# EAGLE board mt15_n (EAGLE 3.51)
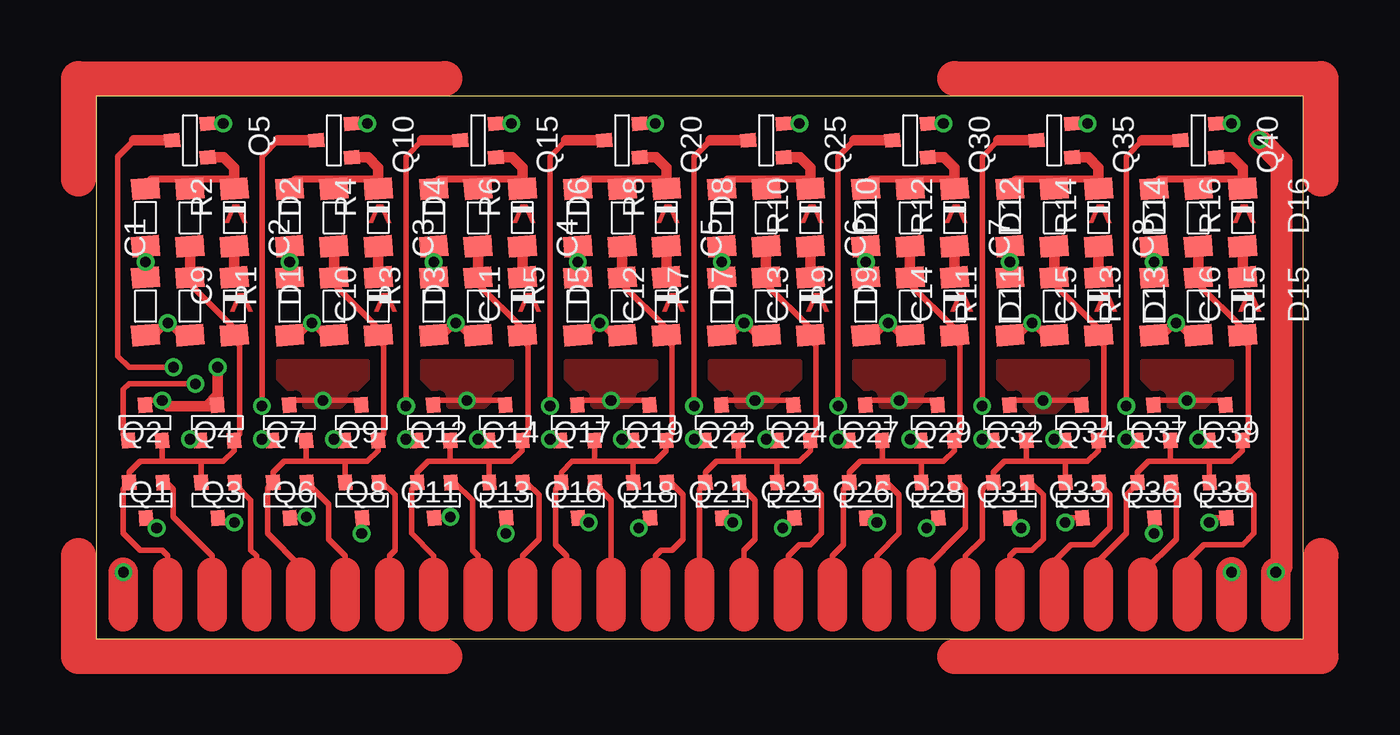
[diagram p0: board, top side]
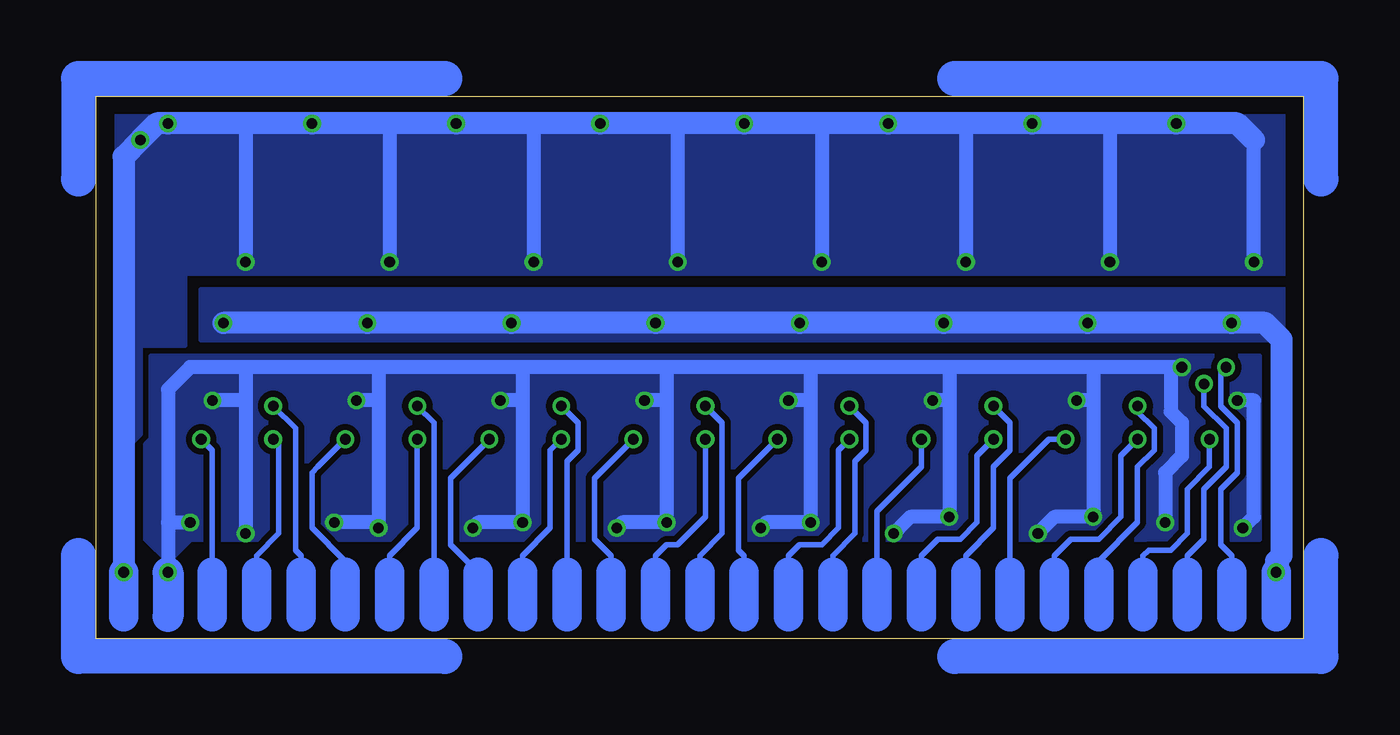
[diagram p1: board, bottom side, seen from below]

Size 69.2 x 31.09 mm. Coordinates in mm from the lower left corner, seen from the top.
Outline: 69.2,0 69.2,31.09 0,31.09 0,0 69.2,0
Copper layers used: Top, Bottom

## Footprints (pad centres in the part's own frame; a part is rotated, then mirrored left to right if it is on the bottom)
04 = smd 1.194 x 1.6 rotated 4.4:  1.651,0 | smd 1.194 x 1.6 rotated 4.3:  -1.651,0
04D = smd 1.194 x 1.6 rotated 4.3:  1.651,0 | smd 1.194 x 1.6 rotated 4.4:  -1.651,0
T-23 = smd 0.787 x 0.889 rotated 4.4:  0.991,1.016 | smd 0.787 x 0.889 rotated 4.3:  -0.94,1.016 | smd 0.787 x 0.889 rotated 4.5:  0.025,-1.016

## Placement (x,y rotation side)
C1  1n  [04]  5.38,24.13 90 top
C2  1n  [04]  13.64,24.13 90 top
C3  1n  [04]  21.89,24.13 90 top
C4  1n  [04]  30.15,24.13 90 top
C5  1n  [04]  38.4,24.13 90 top
C6  1n  [04]  46.66,24.13 90 top
C7  1n  [04]  54.91,24.13 90 top
C8  1n  [04]  63.17,24.13 90 top
C9  100n  [04]  2.84,19.05 270 top
C10  100n  [04]  11.1,19.05 270 top
C11  100n  [04]  19.36,19.05 270 top
C12  100n  [04]  27.61,19.05 270 top
C13  100n  [04]  35.86,19.05 270 top
C14  100n  [04]  44.12,19.05 270 top
C15  100n  [04]  52.38,19.05 270 top
C16  100n  [04]  60.63,19.05 270 top
D1  1N4148  [04D]  7.92,19.05 270 top
D2  1N4148  [04D]  7.92,24.13 270 top
D3  1N4148  [04D]  16.18,19.05 270 top
D4  1N4148  [04D]  16.18,24.13 270 top
D5  1N4148  [04D]  24.44,19.05 270 top
D6  1N4148  [04D]  24.44,24.13 270 top
D7  1N4148  [04D]  32.69,19.05 270 top
D8  1N4148  [04D]  32.69,24.13 270 top
D9  1N4148  [04D]  40.95,19.05 270 top
D10  1N4148  [04D]  40.95,24.13 270 top
D11  1N4148  [04D]  49.2,19.05 270 top
D12  1N4148  [04D]  49.2,24.13 270 top
D13  1N4148  [04D]  57.45,19.05 270 top
D14  1N4148  [04D]  57.45,24.13 270 top
D15  1N4148  [04D]  65.71,19.05 270 top
D16  1N4148  [04D]  65.71,24.13 270 top
Q1  BC857  [T-23]  2.84,12.38 180 top
Q2  BC857  [T-23]  2.84,7.94 0 top
Q3  BC857  [T-23]  6.97,12.38 180 top
Q4  BC857  [T-23]  6.97,7.94 0 top
Q5  BC847  [T-23]  5.38,28.57 270 top
Q6  BC857  [T-23]  11.1,12.38 180 top
Q7  BC857  [T-23]  11.1,7.94 0 top
Q8  BC857  [T-23]  15.23,12.38 180 top
Q9  BC857  [T-23]  15.23,7.94 0 top
Q10  BC847  [T-23]  13.64,28.57 270 top
Q11  BC857  [T-23]  19.36,12.38 180 top
Q12  BC857  [T-23]  19.36,7.94 0 top
Q13  BC857  [T-23]  23.48,12.38 180 top
Q14  BC857  [T-23]  23.48,7.94 0 top
Q15  BC847  [T-23]  21.89,28.57 270 top
Q16  BC857  [T-23]  27.61,12.38 180 top
Q17  BC857  [T-23]  27.61,7.94 0 top
Q18  BC857  [T-23]  31.74,12.38 180 top
Q19  BC857  [T-23]  31.74,7.94 0 top
Q20  BC847  [T-23]  30.15,28.57 270 top
Q21  BC857  [T-23]  35.86,12.38 180 top
Q22  BC857  [T-23]  35.86,7.94 0 top
Q23  BC857  [T-23]  39.99,12.38 180 top
Q24  BC857  [T-23]  39.99,7.94 0 top
Q25  BC847  [T-23]  38.4,28.57 270 top
Q26  BC857  [T-23]  44.12,12.38 180 top
Q27  BC857  [T-23]  44.12,7.94 0 top
Q28  BC857  [T-23]  48.25,12.38 180 top
Q29  BC857  [T-23]  48.25,7.94 0 top
Q30  BC847  [T-23]  46.66,28.57 270 top
Q31  BC857  [T-23]  52.38,12.38 180 top
Q32  BC857  [T-23]  52.38,7.94 0 top
Q33  BC857  [T-23]  56.5,12.38 180 top
Q34  BC857  [T-23]  56.5,7.94 0 top
Q35  BC847  [T-23]  54.91,28.57 270 top
Q36  BC857  [T-23]  60.63,12.38 180 top
Q37  BC857  [T-23]  60.63,7.94 0 top
Q38  BC857  [T-23]  64.76,12.38 180 top
Q39  BC857  [T-23]  64.76,7.94 0 top
Q40  BC847  [T-23]  63.17,28.57 270 top
R1  390  [04]  5.38,19.05 270 top
R2  820  [04]  2.84,24.13 270 top
R3  390  [04]  13.64,19.05 270 top
R4  820  [04]  11.1,24.13 270 top
R5  390  [04]  21.89,19.05 270 top
R6  820  [04]  19.36,24.13 270 top
R7  390  [04]  30.15,19.05 270 top
R8  820  [04]  27.61,24.13 270 top
R9  390  [04]  38.4,19.05 270 top
R10  820  [04]  35.86,24.13 270 top
R11  390  [04]  46.66,19.05 270 top
R12  820  [04]  44.12,24.13 270 top
R13  390  [04]  54.91,19.05 270 top
R14  820  [04]  52.38,24.13 270 top
R15  390  [04]  63.17,19.05 270 top
R16  820  [04]  60.63,24.13 270 top

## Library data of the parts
C1-C16 Q1-Q40 R1-R16 = SMD
D1-D16 = DM

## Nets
0V: Q1. Q2. Q3. Q4. Q6. Q7. Q8. Q9. Q11. Q12. Q13. Q14. Q16. Q17. Q18. Q19. Q21. Q22. Q23. Q24. Q26. Q27. Q28. Q29. Q31. Q32. Q33. Q34. Q36. Q37. Q38. Q39.
A0: Q1.
A1: Q2.
A2: Q3.
A3: Q4.
AQ: Q5.
AX: C1. D1. Q1. Q2. Q3. Q4. R1.
B0: Q6.
B1: Q7.
B2: Q8.
B3: Q9.
BQ: Q10.
BX: C2. D3. Q6. Q7. Q8. Q9. R3.
C0: Q11.
C1: Q12.
C2: Q13.
C3: Q14.
CQ: Q15.
CX: C3. D5. Q11. Q12. Q13. Q14. R5.
D0: Q16.
D1: Q17.
D2: Q18.
D3: Q19.
DQ: Q20.
DX: C4. D7. Q16. Q17. Q18. Q19. R7.
E0: Q21.
E1: Q22.
E2: Q23.
E3: Q24.
EQ: Q25.
EX: C5. D9. Q21. Q22. Q23. Q24. R9.
F0: Q26.
F1: Q27.
F2: Q28.
F3: Q29.
FQ: Q30.
FX: C6. D11. Q26. Q27. Q28. Q29. R11.
G0: Q31.
G1: Q32.
G2: Q33.
G3: Q34.
GND: C9. C10. C11. C12. C13. C14. C15. C16. Q5. Q10. Q15. Q20. Q25. Q30. Q35. Q40. R2. R4. R6. R8. R10. R12. R14. R16.
GQ: Q35.
GX: C7. D13. Q31. Q32. Q33. Q34. R13.
H0: Q36.
H1: Q37.
H2: Q38.
H3: Q39.
HQ: Q40.
HX: C8. D15. Q36. Q37. Q38. Q39. R15.
N$2: D1. D2.
N$3: C1. D2. Q5. R2.
N$6: D3. D4.
N$7: C2. D4. Q10. R4.
N$11: D5. D6.
N$12: C3. D6. Q15. R6.
N$16: D7. D8.
N$17: C4. D8. Q20. R8.
N$21: D9. D10.
N$22: C5. D10. Q25. R10.
N$26: D11. D12.
N$27: C6. D12. Q30. R12.
N$31: D13. D14.
N$32: C7. D14. Q35. R14.
N$36: D15. D16.
N$37: C8. D16. Q40. R16.
VCC: C9. C10. C11. C12. C13. C14. C15. C16. R1. R3. R5. R7. R9. R11. R13. R15.

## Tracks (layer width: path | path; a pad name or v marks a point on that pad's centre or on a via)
0V  (via drill 0.61 pad 1.02)
  Top 0.305: Q2. 2.91,6.92 v3.48,6.35 | Q7. 11.16,6.92 11.23,6.99 v12.05,6.99 | Q9. 15.29,6.92 15.23,6.86 v15.23,6.03 | Q4. 7.04,6.92 6.97,6.86 7.1,6.86 7.29,6.67 v7.93,6.67 | 23.55,6.92 Q14. 23.48,6.9 v23.48,6.03 | 40.06,6.92 Q24. 39.93,6.92 v39.36,6.35 | 48.31,6.92 Q29. 48.18,6.92 v47.61,6.35 | 64.82,6.92 Q39. 64.06,6.92 v63.81,6.67 | 56.57,6.92 Q34. 55.8,6.92 v55.55,6.67 | Q19. 31.67,6.92 v31.1,6.35 | Q1. 2.91,13.4 3.16,13.65 v3.8,13.65 | Q6. 11.16,13.4 11.42,13.65 v13.01,13.65 14.91,13.65 15.16,13.4 Q8. | Q11. 19.42,13.4 19.67,13.65 v21.26,13.65 23.16,13.65 23.42,13.4 Q13. | Q16. 27.67,13.4 27.93,13.65 v29.51,13.65 31.42,13.65 31.67,13.4 Q18. | Q21. 35.93,13.4 36.18,13.65 v37.77,13.65 39.68,13.65 39.93,13.4 Q23. | Q26. 44.18,13.4 44.44,13.65 v46.03,13.65 47.93,13.65 48.18,13.4 Q28. | Q31. 52.44,13.4 52.69,13.65 v54.28,13.65 56.18,13.65 56.44,13.4 Q33. | Q36. 60.69,13.4 60.95,13.65 v62.53,13.65 64.44,13.65 64.69,13.4 Q38. | Q12. 20.24,6.92 v20.31,6.99 | Q17. 27.99,6.92 v28.25,6.67 | Q22. 36.25,6.92 v36.5,6.67 | Q27. 44.5,6.92 v44.75,6.67 | Q32. 52.44,6.92 v53.01,6.35 | Q37. 60.66,6.06 v60.63,6.03
  Top 0.61: v3.8,13.65 4.12,13.34 6.34,13.34 | Q3. 6.88,13.34 6.34,13.34 | 6.34,13.34 6.97,13.97 v6.97,15.56
  Top 1.778: v65.08,3.81 65.08,1.27
  Bottom 0.813: v3.48,6.35 2.84,6.99 2.84,13.65 v3.8,13.65 | v7.93,6.67 7.93,9.53 6.97,10.48 6.97,12.38 7.61,13.02 7.61,15.56 | v15.23,6.03 14.27,6.99 v12.05,6.99 12.05,13.65 | 12.05,13.65 v13.01,13.65 | 12.05,15.56 12.05,13.65 | 7.61,15.56 12.05,15.56 | v6.97,15.56 7.61,15.56 | 12.05,15.56 20.31,15.56 | 20.31,15.56 28.25,15.56 | 28.25,15.56 36.5,15.56 | 36.5,15.56 44.75,15.56 | 20.31,13.65 v20.31,6.99 22.53,6.99 v23.48,6.03 | 20.31,15.56 20.31,13.65 | 20.31,13.65 v21.26,13.65 | v31.1,6.35 30.78,6.67 v28.25,6.67 28.25,13.65 | 28.25,15.56 28.25,13.65 | 28.25,13.65 v29.51,13.65 | 36.5,13.65 v36.5,6.67 39.04,6.67 v39.36,6.35 | 36.5,15.56 36.5,13.65 | 36.5,13.65 v37.77,13.65 | 44.75,13.65 v44.75,6.67 47.29,6.67 v47.61,6.35 | 44.75,15.56 44.75,13.65 | 44.75,13.65 v46.03,13.65 | 65.08,6.67 65.08,14.29 63.81,15.56 60.63,15.56 | 65.08,6.67 v65.08,3.81 | 44.75,15.56 53.01,15.56 | 53.01,15.56 60.63,15.56 | 53.01,6.67 v53.01,6.35 | 53.01,13.65 53.01,6.67 | 53.01,13.65 v54.28,13.65 | 53.01,15.56 53.01,13.65 | 60.63,13.65 v60.63,6.03 | 60.63,15.56 60.63,13.65 | 60.63,13.65 v62.53,13.65 | 65.08,6.67 v63.81,6.67 | 53.01,6.67 v55.55,6.67
  Bottom 1.778: v65.08,3.81 65.08,1.27
  pour Bottom (isolate 0.356): 65.08,4.45 63.8,5.71 2.53,5.71 2.53,16.19 66.03,16.19 66.03,11.43 66.34,11.11 66.34,5.71
  pour Top (isolate 0.356): 10.46,15.88 15.54,15.88 15.54,14.92 13.96,13.34 12.05,13.34 10.46,14.92
  pour Top (isolate 0.356): 18.72,15.88 18.72,14.92 20.31,13.34 22.21,13.34 23.8,14.92 23.8,15.88
  pour Top (isolate 0.356): 26.98,15.88 32.05,15.88 32.05,14.92 30.47,13.34 28.56,13.34 26.98,14.92
  pour Top (isolate 0.356): 35.23,15.88 35.23,14.92 36.82,13.34 38.72,13.34 40.31,14.92 40.31,15.88
  pour Top (isolate 0.356): 43.48,15.88 48.56,15.88 48.56,14.92 46.98,13.34 45.07,13.34 43.48,14.92
  pour Top (isolate 0.356): 51.74,15.88 56.82,15.88 56.82,14.92 54.91,13.02 53.64,13.02 51.74,14.92
  pour Top (isolate 0.356): 59.99,15.88 65.08,15.88 65.08,14.92 63.49,13.34 61.58,13.34 59.99,14.92
A0  (via drill 0.61 pad 1.02)
  Top 0.305: 1.85,11.37 1.85,11.47 1.57,11.75 1.57,14.29 1.89,14.61 v5.7,14.61
  Bottom 0.305: 6.66,3.81 6.66,4.76 5.7,5.71 5.7,8.57 4.43,9.84 4.43,12.06 5.7,13.34 v5.7,14.61
  Bottom 1.676: 6.66,1.27 6.66,3.81
A1
  Top 0.305: 6.66,3.81 6.66,4.76 4.43,6.99 4.43,8.57 4.05,8.95 3.84,8.95
  Top 1.676: 6.66,1.27 6.66,3.81
A2  (via drill 0.61 pad 1.02)
  Top 0.305: 5.98,11.37 5.45,11.37 v5.38,11.43
  Bottom 0.305: 9.19,3.81 9.19,4.76 8.88,5.08 7.61,5.08 6.66,6.03 6.66,8.57 5.38,9.84 v5.38,11.43
  Bottom 1.676: 9.19,1.27 9.19,3.81
A3
  Top 0.305: 7.96,8.95 7.96,8.85 8.88,7.94 8.88,5.08 9.19,4.76 9.19,3.81
  Top 1.676: 9.19,1.27 9.19,3.81
AQ  (via drill 0.61 pad 1.02)
  Top 0.305: 2.18,28.55 1.26,27.62 1.26,16.19 1.89,15.56 v4.43,15.56
  Top 0.61: 2.18,28.55 Q5.
  Bottom 0.305: 4.12,3.81 4.12,4.76 4.75,5.4 4.75,8.57 3.8,9.53 3.8,12.38 4.75,13.34 4.75,15.24 v4.43,15.56
  Bottom 1.676: 4.12,1.27 4.12,3.81
AX
  Top 0.305: R1. 5.38,20.32 7.93,17.78 7.93,17.4 7.93,17.14 8.24,16.83 8.24,11.75 7.91,11.42 7.91,11.37 7.91,10.78 7.29,10.16 6.02,10.16 | 4.12,3.81 4.12,4.76 3.8,5.08 2.53,5.08 1.57,6.03 1.57,8.57 1.91,8.9 1.91,8.95 1.91,9.54 2.53,10.16 3.8,10.16 | 3.8,10.16 6.02,10.16 | 3.78,11.37 3.8,11.35 3.8,10.16 | 6.03,8.95 6.02,8.97 6.02,10.16
  Top 0.61: R1. C1.
  Top 1.676: 4.12,1.27 4.12,3.81
B0  (via drill 0.61 pad 1.02)
  Top 0.305: 10.11,11.37 9.58,11.37 v9.51,11.43
  Bottom 0.305: 14.27,3.81 14.27,4.76 13.32,5.71 11.74,5.71 10.46,6.99 10.46,10.48 v9.51,11.43
  Bottom 1.676: 14.27,1.27 14.27,3.81
B1
  Top 0.305: 12.09,8.95 13.32,7.72 13.32,5.71 14.27,4.76 14.27,3.81
  Top 1.676: 14.27,1.27 14.27,3.81
B2  (via drill 0.61 pad 1.02)
  Top 0.305: 14.24,11.37 13.7,11.37 v13.64,11.43
  Bottom 0.305: 16.82,3.81 16.82,9.21 14.59,11.43 v13.64,11.43
  Bottom 1.676: 16.82,1.27 16.82,3.81
B3
  Top 0.305: 16.22,8.95 16.43,8.95 17.13,8.26 17.13,5.08 16.82,4.76 16.82,3.81
  Top 1.676: 16.82,1.27 16.82,3.81
BQ  (via drill 0.61 pad 1.02)
  Top 0.305: 10.44,28.55 9.51,27.62 v9.51,13.34
  Top 0.61: 10.44,28.55 Q10.
  Bottom 0.305: 11.74,3.81 11.74,4.45 9.51,6.67 9.51,9.84 8.56,10.79 8.56,12.06 9.51,13.02 v9.51,13.34
  Bottom 1.676: 11.74,1.27 11.74,3.81
BX
  Top 0.305: R3. 13.64,20.32 16.18,17.78 16.18,17.4 16.18,17.14 16.5,16.83 16.5,11.75 16.17,11.42 16.17,11.37 16.17,10.78 15.54,10.16 14.27,10.16 | 11.74,3.81 11.74,4.13 9.83,6.03 9.83,8.62 10.16,8.95 10.16,9.54 10.78,10.16 12.05,10.16 | 12.05,10.16 14.27,10.16 | 12.04,11.37 12.05,11.35 12.05,10.16 | 14.29,8.95 14.27,8.97 14.27,10.16
  Top 0.61: R3. C2.
  Top 1.676: 11.74,1.27 11.74,3.81
C0  (via drill 0.61 pad 1.02)
  Top 0.305: 18.36,11.37 17.83,11.37 v17.77,11.43
  Bottom 0.305: v17.77,11.43 18.72,10.48 18.72,6.67 19.67,5.71 20.94,5.71 21.89,4.76 21.89,3.81
  Bottom 1.676: 21.89,1.27 21.89,3.81
C1
  Top 0.305: 20.35,8.95 20.56,8.95 21.58,7.94 21.58,5.08 21.89,4.76 21.89,3.81
  Top 1.676: 21.89,1.27 21.89,3.81
C2  (via drill 0.61 pad 1.02)
  Top 0.305: 22.49,11.37 21.96,11.37 v21.89,11.43
  Bottom 0.305: 24.44,3.81 24.44,7.3 21.89,9.84 v21.89,11.43
  Bottom 1.676: 24.44,1.27 24.44,3.81
C3
  Top 0.305: 24.47,8.95 24.69,8.95 25.39,8.26 25.39,5.71 24.44,4.76 24.44,3.81
  Top 1.676: 24.44,1.27 24.44,3.81
CQ  (via drill 0.61 pad 1.02)
  Top 0.305: 18.69,28.55 17.77,27.62 v17.77,13.34
  Top 0.61: 18.69,28.55 Q15.
  Bottom 0.305: 19.35,3.81 19.35,4.76 17.77,6.35 17.77,9.84 16.82,10.79 16.82,12.38 v17.77,13.34
  Bottom 1.676: 19.35,1.27 19.35,3.81
CX
  Top 0.305: R5. 21.89,20.32 24.44,17.78 24.44,17.4 24.44,17.14 24.75,16.83 24.75,11.75 24.42,11.42 24.42,11.37 24.42,10.78 23.8,10.16 22.53,10.16 | 20.31,10.16 19.04,10.16 18.42,9.54 18.42,8.95 18.42,8.9 18.09,8.57 18.09,6.03 19.35,4.76 19.35,3.81 | 20.31,10.16 22.53,10.16 | 22.54,8.95 22.53,8.97 22.53,10.16 | 20.29,11.37 20.31,11.35 20.31,10.16
  Top 0.61: R5. C3.
  Top 1.676: 19.35,1.27 19.35,3.81
D0  (via drill 0.61 pad 1.02)
  Top 0.305: 26.62,11.37 26.09,11.37 v26.02,11.43
  Bottom 0.305: 29.51,3.81 29.51,4.76 28.88,5.4 27.61,5.4 26.66,6.35 26.66,10.79 v26.02,11.43
  Bottom 1.676: 29.51,1.27 29.51,3.81
D1
  Top 0.305: 28.6,8.95 28.6,8.85 29.51,7.94 29.51,3.81
  Top 1.676: 29.51,1.27 29.51,3.81
D2  (via drill 0.61 pad 1.02)
  Top 0.305: 30.75,11.37 30.21,11.37 v30.15,11.43
  Bottom 0.305: 32.06,3.81 32.06,4.76 32.37,5.08 32.37,9.21 v30.15,11.43
  Bottom 1.676: 32.06,1.27 32.06,3.81
D3
  Top 0.305: 32.73,8.95 32.94,8.95 33.64,8.26 33.64,5.71 33.01,5.08 32.37,5.08 32.06,4.76 32.06,3.81
  Top 1.676: 32.06,1.27 32.06,3.81
DQ  (via drill 0.61 pad 1.02)
  Top 0.305: 26.95,28.55 26.02,27.62 v26.02,13.34
  Top 0.61: 26.95,28.55 Q20.
  Bottom 0.305: 26.98,3.81 26.98,4.76 25.71,6.03 25.71,10.16 25.07,10.79 25.07,12.38 v26.02,13.34
  Bottom 1.676: 26.98,1.27 26.98,3.81
DX
  Top 0.305: 30.15,20.64 30.15,20.32 32.69,17.78 32.69,17.4 32.69,17.14 33.01,16.83 33.01,11.75 32.68,11.42 32.68,11.37 32.68,10.78 32.06,10.16 30.78,10.16 | 28.56,10.16 27.29,10.16 26.67,9.54 26.67,8.95 26.67,8.9 26.34,8.57 26.34,5.4 26.98,4.76 26.98,3.81 | 28.55,11.37 28.56,11.35 28.56,10.16 | 28.56,10.16 30.78,10.16 | 30.8,8.95 30.78,8.97 30.78,10.16
  Top 0.61: 30.15,20.64 R7. C4.
  Top 1.676: 26.98,1.27 26.98,3.81
E0  (via drill 0.61 pad 1.02)
  Top 0.305: 34.87,11.37 34.34,11.37 v34.28,11.43
  Bottom 0.305: 37.14,3.81 37.14,4.76 36.5,5.4 35.86,5.4 34.28,6.99 v34.28,11.43
  Bottom 1.676: 37.14,1.27 37.14,3.81
E1
  Top 0.305: 36.86,8.95 36.86,8.85 37.77,7.94 37.77,5.71 37.14,5.08 37.14,3.81
  Top 1.676: 37.14,1.27 37.14,3.81
E2  (via drill 0.61 pad 1.02)
  Top 0.305: 39,11.37 38.47,11.37 v38.4,11.43
  Bottom 0.305: 39.68,3.81 39.68,4.76 40.63,5.71 40.63,9.21 v38.4,11.43
  Bottom 1.676: 39.68,1.27 39.68,3.81
E3
  Top 0.305: 40.98,8.95 40.98,8.85 41.58,8.26 41.58,6.03 40.95,5.4 40.31,5.4 39.68,4.76 39.68,3.81
  Top 1.676: 39.68,1.27 39.68,3.81
EQ  (via drill 0.61 pad 1.02)
  Top 0.305: 35.2,28.55 34.28,27.62 v34.28,13.34
  Top 0.61: 35.2,28.55 Q25.
  Bottom 0.305: 34.6,3.81 34.6,4.76 33.32,6.03 33.32,12.38 v34.28,13.34
  Bottom 1.676: 34.6,1.27 34.6,3.81
EX
  Top 0.305: R9. 38.4,20.32 40.95,17.78 40.95,17.4 40.95,17.14 41.26,16.83 41.26,11.75 40.93,11.42 40.93,11.37 40.93,10.78 40.31,10.16 39.04,10.16 | 36.82,10.16 35.55,10.16 34.93,9.54 34.93,8.95 34.93,8.9 34.6,8.57 34.6,3.81 | 36.82,10.16 39.04,10.16 | 36.8,11.37 36.82,11.35 36.82,10.16 | 39.05,8.95 39.04,8.97 39.04,10.16
  Top 0.61: R9. C5.
  Top 1.676: 34.6,1.27 34.6,3.81
F0  (via drill 0.61 pad 1.02)
  Top 0.305: 43.13,11.37 43.07,11.43 v42.53,11.43
  Bottom 0.305: 44.75,3.81 44.75,4.76 43.17,6.35 43.17,10.79 v42.53,11.43
  Bottom 1.676: 44.75,1.27 44.75,3.81
F1
  Top 0.305: 45.11,8.95 45.33,8.95 46.03,8.26 46.03,6.03 44.75,4.76 44.75,3.81
  Top 1.676: 44.75,1.27 44.75,3.81
F2  (via drill 0.61 pad 1.02)
  Top 0.305: 47.26,11.37 47.19,11.43 v46.66,11.43
  Bottom 0.305: 47.29,3.81 48.88,5.4 48.88,9.21 v46.66,11.43
  Bottom 1.676: 47.29,1.27 47.29,3.81
F3
  Top 0.305: 49.24,8.95 49.45,8.95 49.83,8.57 49.83,6.35 47.29,3.81
  Top 1.676: 47.29,1.27 47.29,3.81
FQ  (via drill 0.61 pad 1.02)
  Top 0.305: 43.46,28.55 42.53,27.62 v42.53,13.34
  Top 0.61: 43.46,28.55 Q30.
  Bottom 0.305: 42.21,3.81 42.21,10.16 41.58,10.79 41.58,12.38 v42.53,13.34
  Bottom 1.676: 42.21,1.27 42.21,3.81
FX
  Top 0.305: R11. 46.66,20.32 49.2,17.78 49.2,17.4 49.2,17.14 49.52,16.83 49.52,11.75 49.19,11.42 49.19,11.37 49.19,10.78 48.57,10.16 47.29,10.16 | 45.07,10.16 43.8,10.16 43.18,9.54 43.18,8.95 43.18,8.9 42.85,8.57 42.85,5.4 42.21,4.76 42.21,3.81 | 45.07,10.16 47.29,10.16 | 47.31,8.95 47.29,8.97 47.29,10.16 | 45.06,11.37 45.07,11.35 45.07,10.16
  Top 0.61: R11. C6.
  Top 1.676: 42.21,1.27 42.21,3.81
G0  (via drill 0.61 pad 1.02)
  Top 0.305: 51.38,11.37 50.85,11.37 v50.79,11.43
  Bottom 0.305: 52.38,3.81 52.38,4.76 50.79,6.35 v50.79,11.43
  Bottom 1.676: 52.38,1.27 52.38,3.81
G1
  Top 0.305: 53.37,8.95 53.58,8.95 54.28,8.26 54.28,5.71 53.64,5.08 52.69,5.08 52.38,4.76 52.38,3.81
  Top 1.676: 52.38,1.27 52.38,3.81
G2  (via drill 0.61 pad 1.02)
  Top 0.305: 55.51,11.37 54.98,11.37 v54.92,11.43
  Bottom 0.305: 54.92,3.81 54.92,4.45 56.82,6.35 56.82,9.53 56.5,9.84 v54.92,11.43
  Bottom 1.676: 54.92,1.27 54.92,3.81
G3
  Top 0.305: 57.49,8.95 57.49,8.85 58.09,8.26 58.09,6.35 57.14,5.4 55.87,5.4 54.92,4.45 54.92,3.81
  Top 1.676: 54.92,1.27 54.92,3.81
GND  (via drill 0.61 pad 1.02)
  Top 0.305: 6.4,29.52 7.28,29.52 v7.29,29.53 | 14.66,29.52 15.53,29.52 v15.54,29.53 | 22.91,29.52 23.79,29.52 v23.8,29.53 | 31.17,29.52 32.04,29.52 v32.06,29.53 | 39.42,29.52 40.3,29.52 v40.31,29.53 | 47.68,29.52 48.55,29.52 v48.57,29.53 | 55.93,29.52 56.81,29.52 v56.82,29.53 | 64.19,29.52 65.06,29.52 v65.08,29.53
  Top 0.61: C9. v2.84,21.59 2.84,22.48 | C10. v11.1,21.59 11.1,22.48 | C11. v19.35,21.59 19.35,22.48 | C12. v27.61,21.59 27.61,22.48 | C13. v35.86,21.59 35.86,22.48 | C14. v44.12,21.59 44.12,22.48 | 52.38,20.64 C15. v52.38,21.59 52.38,22.48 | C16. v60.63,21.59 60.63,22.48
  Top 1.27: v67.61,3.81 67.93,4.13 67.93,27.3 v66.66,28.57
  Top 1.676: v67.61,3.81 67.61,1.27
  Bottom 0.813: v2.84,21.59 2.84,28.57 | 11.1,29.53 v11.1,21.59 | 19.35,29.53 v19.35,21.59 | 27.61,29.53 v27.61,21.59 | 35.86,29.53 v35.86,21.59 | 44.12,29.53 v44.12,21.59 | 52.38,29.53 v52.38,21.59 | 60.63,29.53 v60.63,21.59
  Bottom 1.27: v67.61,3.81 67.61,27.62 v66.66,28.57 65.71,29.53 v65.08,29.53 60.63,29.53 v56.82,29.53 52.38,29.53 v48.57,29.53 44.12,29.53 v40.31,29.53 35.86,29.53 v32.06,29.53 27.61,29.53 v23.8,29.53 19.35,29.53 v15.54,29.53 11.1,29.53 v7.29,29.53 3.8,29.53 2.84,28.57
  Bottom 1.676: v67.61,3.81 67.61,1.27
  pour Bottom (isolate 0.356): 0.62,30.48 0.62,20.95 64.12,20.95 64.12,16.83 66.66,16.83 66.66,11.75 67.3,11.11 67.3,0.95 68.57,0.95 68.57,30.48
GQ  (via drill 0.61 pad 1.02)
  Top 0.305: 51.71,28.55 50.79,27.62 v50.79,13.34
  Top 0.61: 51.71,28.55 Q35.
  Bottom 0.305: 49.83,3.81 49.83,12.38 v50.79,13.34
  Bottom 1.676: 49.83,1.27 49.83,3.81
GX
  Top 0.305: R13. 54.92,20.32 57.46,17.78 57.46,17.4 57.46,17.14 57.77,16.83 57.77,11.75 57.44,11.42 57.44,11.37 57.44,10.78 56.82,10.16 55.55,10.16 | 53.33,10.16 52.06,10.16 51.44,9.54 51.44,8.95 51.17,8.95 50.79,8.57 50.79,5.71 49.83,4.76 49.83,3.81 | 53.33,10.16 55.55,10.16 | 55.56,8.95 55.55,8.97 55.55,10.16 | 53.31,11.37 53.33,11.35 53.33,10.16
  Top 0.61: R13. C7.
  Top 1.676: 49.83,1.27 49.83,3.81
H0  (via drill 0.61 pad 1.02)
  Top 0.305: 59.64,11.37 59.11,11.37 v59.04,11.43
  Bottom 0.305: 60,3.81 60,4.76 58.72,6.03 58.72,11.11 v59.04,11.43
  Bottom 1.676: 60,1.27 60,3.81
H1
  Top 0.305: 60,3.81 61.9,5.71 61.9,8.57 61.62,8.85 61.62,8.95
  Top 1.676: 60,1.27 60,3.81
H2  (via drill 0.61 pad 1.02)
  Top 0.305: 63.77,11.37 63.23,11.37 v63.17,11.43
  Bottom 0.305: 62.53,3.81 62.53,10.79 v63.17,11.43
  Bottom 1.676: 62.53,1.27 62.53,3.81
H3
  Top 0.305: 62.53,3.81 62.53,4.45 63.49,5.4 65.71,5.4 66.35,6.03 66.35,8.26 65.75,8.85 65.75,8.95
  Top 1.676: 62.53,1.27 62.53,3.81
HQ  (via drill 0.61 pad 1.02)
  Top 0.305: 59.97,28.55 59.04,27.62 v59.04,13.34
  Top 0.61: 59.97,28.55 Q40.
  Bottom 0.305: 57.46,3.81 57.46,4.76 57.77,5.08 57.77,12.06 v59.04,13.34
  Bottom 1.676: 57.46,1.27 57.46,3.81
HX
  Top 0.305: R15. 63.17,20.32 65.71,17.78 65.71,17.4 65.71,17.14 66.03,16.83 66.03,11.75 65.7,11.42 65.7,11.37 65.7,10.78 65.08,10.16 63.81,10.16 | 61.58,10.16 63.81,10.16 | 61.58,10.16 60.31,10.16 59.69,9.54 59.69,8.95 59.69,8.9 59.04,8.26 59.04,6.03 57.46,4.45 57.46,3.81 | 61.57,11.37 61.58,11.35 61.58,10.16 | 63.82,8.95 63.81,8.97 63.81,10.16
  Top 0.61: R15. C8.
  Top 1.676: 57.46,1.27 57.46,3.81
N$2
  Top 0.61: 7.93,22.48 D1.
N$3
  Top 0.406: 6.4,27.58 6.38,27.58 | 5.38,26.35 7.93,26.35 D2. | R2. 2.84,26.04 3.16,26.35 5.38,26.35 | 5.38,26.35 5.38,25.78
  Top 0.61: 7.93,26.35 7.93,26.99 7.33,27.58 6.4,27.58
N$6
  Top 0.61: 16.18,22.48 D3.
N$7
  Top 0.406: 14.66,27.58 14.63,27.58 | 13.64,26.35 16.18,26.35 D4. | R4. 11.1,26.04 11.42,26.35 13.64,26.35 | 13.64,26.35 13.64,25.78
  Top 0.61: 16.18,26.35 16.18,26.99 15.58,27.58 14.66,27.58
N$11
  Top 0.61: 24.44,22.48 D5.
N$12
  Top 0.406: 22.91,27.58 22.89,27.58 | 21.89,26.35 24.44,26.35 D6. | R6. 19.35,26.04 19.67,26.35 21.89,26.35 | 21.89,26.35 21.89,25.78
  Top 0.61: 24.44,26.35 24.44,26.99 23.84,27.58 22.91,27.58
N$16
  Top 0.61: 32.69,22.48 D7.
N$17
  Top 0.406: 31.17,27.58 31.14,27.58 | 30.15,26.35 32.69,26.35 D8. | R8. 27.61,26.04 27.93,26.35 30.15,26.35 | 30.15,26.35 30.15,25.78
  Top 0.61: 32.69,26.35 32.69,26.99 32.09,27.58 31.17,27.58
N$21
  Top 0.61: 40.95,22.48 D9.
N$22
  Top 0.406: 39.42,27.58 39.4,27.58 | R10. 35.86,26.04 36.18,26.35 38.4,26.35 | 38.4,26.35 40.95,26.35 D10. | 38.4,26.35 38.4,25.78
  Top 0.61: 40.95,26.35 40.95,26.99 40.35,27.58 39.42,27.58
N$26
  Top 0.61: 49.2,22.48 D11.
N$27
  Top 0.406: 47.68,27.58 47.65,27.58 | 46.66,26.35 49.2,26.35 D12. | R12. 44.12,26.04 44.44,26.35 46.66,26.35 | 46.66,26.35 46.66,25.78
  Top 0.61: 49.2,26.35 49.2,26.99 48.6,27.58 47.68,27.58
N$31
  Top 0.61: 57.46,22.48 D13.
N$32
  Top 0.406: 55.93,27.58 55.91,27.58 | 54.92,26.35 57.46,26.35 D14. | 54.92,26.35 54.92,25.78 | R14. 52.38,26.04 52.69,26.35 54.92,26.35
  Top 0.61: 55.93,27.58 56.86,27.58 57.46,26.99 57.46,26.35
N$36
  Top 0.61: 65.71,22.48 D15.
N$37
  Top 0.406: 64.19,27.58 64.16,27.58 | 63.17,26.35 65.71,26.35 D16. | R16. 60.63,26.04 60.95,26.35 63.17,26.35 | 63.17,26.35 63.17,25.78
  Top 0.61: 65.71,26.35 65.71,26.99 65.11,27.58 64.19,27.58
S$1
  Top 2: 70.2,4.76 70.2,-1 49.2,-1
S$2
  Top 2: 70.2,26.34 70.2,32.09 49.2,32.09
S$3
  Top 2: -1,4.76 -1,-1 20,-1
S$4
  Top 2: 20,32.09 -1,32.09 -1,26.34
S$5
  Bottom 2: 70.2,4.76 70.2,-1 49.2,-1
S$6
  Bottom 2: 70.2,26.34 70.2,32.09 49.2,32.09
S$7
  Bottom 2: -1,4.76 -1,-1 20,-1
S$8
  Bottom 2: 20,32.09 -1,32.09 -1,26.34
VCC  (via drill 0.61 pad 1.02)
  Top 0.305: 63.17,17.4 62.6,17.4 v61.9,18.1 61.2,17.4 60.63,17.4 | 54.92,17.4 54.34,17.4 v53.64,18.1 52.95,17.4 52.38,17.4 | 44.12,17.4 44.69,17.4 v45.39,18.1 46.09,17.4 46.66,17.4 | 38.4,17.4 37.83,17.4 v37.14,18.1 36.44,17.4 35.86,17.4 | 19.35,17.4 19.93,17.4 v20.62,18.1 21.32,17.4 21.89,17.4 | 27.61,17.4 28.18,17.4 v28.88,18.1 29.58,17.4 30.15,17.4 | 2.84,17.4 3.42,17.4 v4.12,18.1 4.81,17.4 5.38,17.4 | 11.1,17.4 11.67,17.4 v12.37,18.1 13.07,17.4 13.64,17.4
  Top 1.676: v1.57,3.81 1.57,1.27
  Bottom 1.27: v1.57,3.81 1.57,4.45 1.26,4.76 1.26,17.14 2.21,18.1 v4.12,18.1 v12.37,18.1 v20.62,18.1 v28.88,18.1 v37.14,18.1 v45.39,18.1 v53.64,18.1 v61.9,18.1
  Bottom 1.676: 1.57,1.27 v1.57,3.81
  pour Bottom (isolate 0.356): 0.94,20 63.17,20 63.17,17.14 0.94,17.14

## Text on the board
Top: ^ | ^ | ^ | ^ | ^ | ^ | ^ | ^ | ^ | ^ | ^ | ^ | ^ | ^ | ^ | ^
Document: top | VCC | AX | A1 | A3 | BX | B1 | B3 | CX | C1 | C3 | DX | D1 | D3 | EX | E1 | E3 | FX | F1 | F3 | GX | G1 | G3 | HX | H1 | H3 | 0V | GND | bot | VCC | AQ | A0 | A2 | BQ | B0 | B2 | CQ | C0 | C2 | DQ | D0 | D2 | EQ | E0 | E2 | FQ | F0 | F2 | GQ | G0 | G2 | HQ | H0 | H2 | 0V | GND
